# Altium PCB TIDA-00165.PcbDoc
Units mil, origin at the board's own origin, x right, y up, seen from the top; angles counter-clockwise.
Board outline 2800 x 235.83 mil, 4 copper layers (Top Layer, GND, VCC, Bottom Layer), stack 90 mil thick; 67 components, 45 nets, 220 pads, 72 vias.
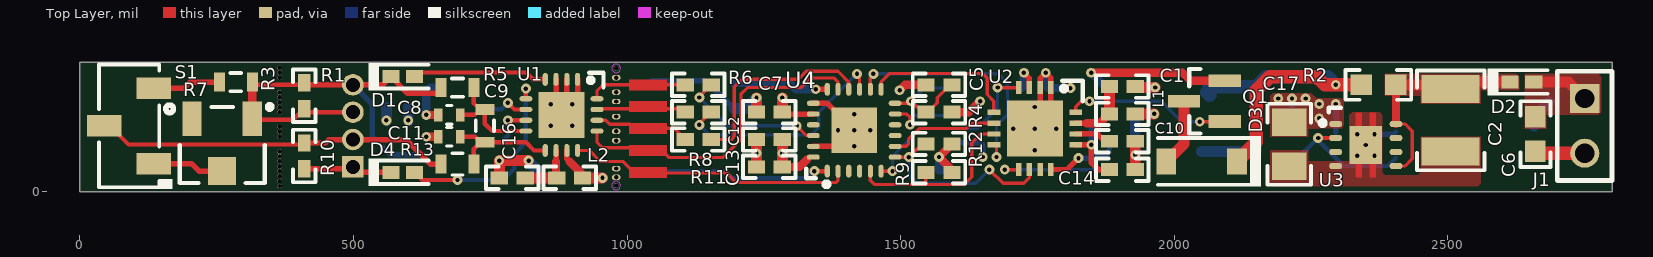
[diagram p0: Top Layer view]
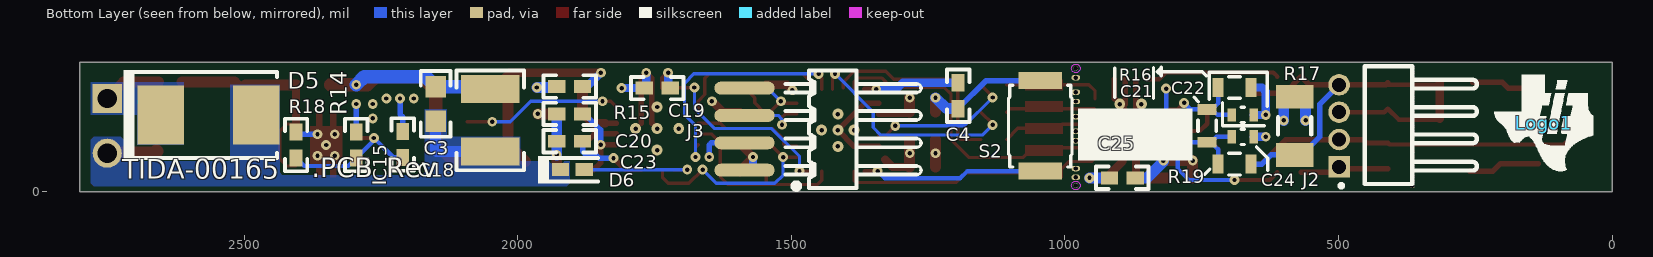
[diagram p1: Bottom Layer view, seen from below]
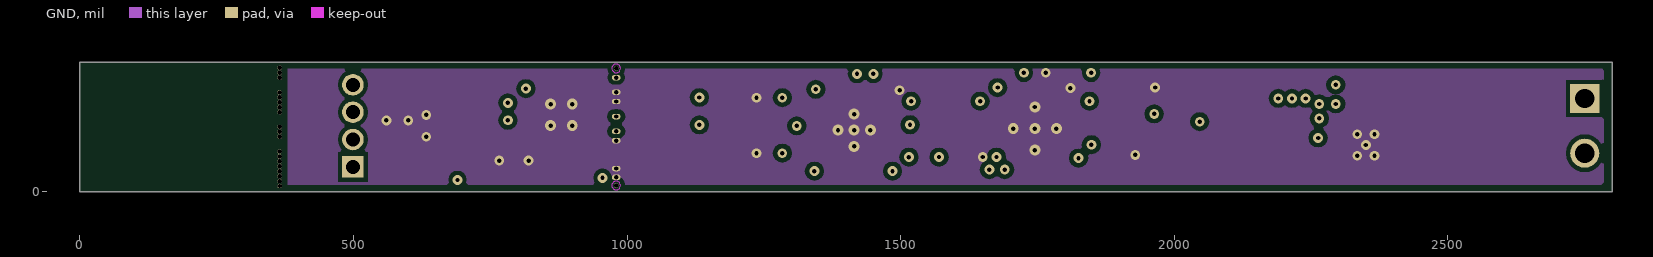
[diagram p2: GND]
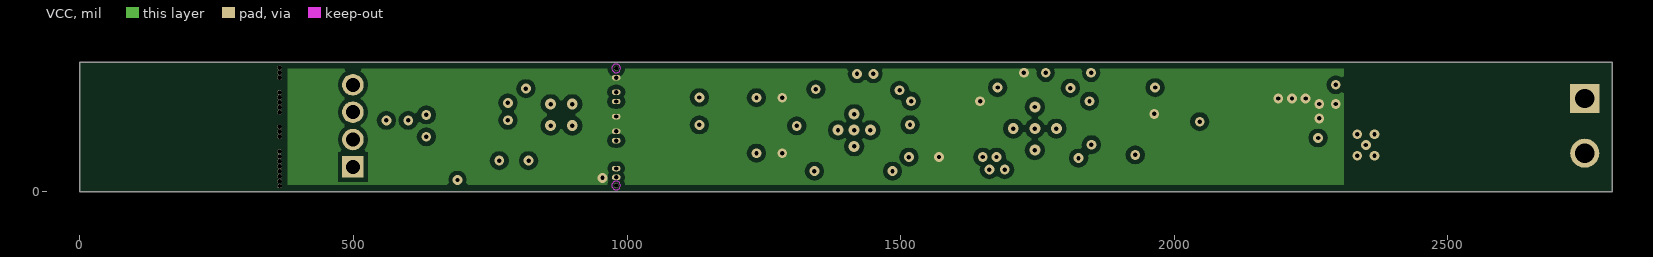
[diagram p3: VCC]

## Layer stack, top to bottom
Top Layer: signal copper 1.4
Dielectric: core 59.2, FR-4, Dk 4.8
GND: signal copper 1.4
Dielectric: prepreg 12.6, FR-4, Dk 4.8
VCC: signal copper 1.4
Dielectric: core 12.6, FR-4, Dk 4.8
Bottom Layer: signal copper 1.4

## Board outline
0,0 2800,0 2800,235.83 0,235.83

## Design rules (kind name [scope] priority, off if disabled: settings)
Clearance "Copper to 25.59 Mils Drill" [InPolygon] p1: gap=8
Clearance [All] p2: gap=4.92
DiffPairsRouting [All] p1: maxlimit=393.7 minlimit=4.92 mostfreqgap=5.91 maxuncoupledlength=500
FabricationTestPointUsage FabricationTestPointUsage_1 [All] p1: valid=0 allowmultiple=FALSE
FabricationTestpoint FabricationTestpoint_1 [All] p1: side=3 testpointundercomponent=TRUE minsize=40 maxsize=100 preferedsize=60 minholesize=0 maxholesize=40 preferedholesize=32 testpointgrid=1 allowsidetop=TRUE allowsidebottom=TRUE usegrid=TRUE gridtolerance=0.01
HoleSize [All] p1: absolutevalues=TRUE maxlimit=236.22 minlimit=7.87 maxpercent=80.000 minpercent=20.000
HoleSize FabricationTestpoint [All] p2 off: absolutevalues=TRUE maxlimit=100 minlimit=1 maxpercent=80.000 minpercent=20.000
HoleSize FabricationTestPointUsage [All] p3 off: absolutevalues=TRUE maxlimit=100 minlimit=1 maxpercent=80.000 minpercent=20.000
PlaneClearance [All] p1: clearance=19.68
PlaneConnect [All] p1: planeconnectstyle=Relief reliefexpansion=15.75 reliefentries=4 reliefconductorwidth=5.91 reliefairgap=5.91
PolygonConnect [All] p1: connectstyle=Direct reliefconductorwidth=5.91 reliefentries=4 polygonreliefangle="90 Angle" airgapwidth=10
RoutingCorners [All] p1: cornerstyle=45-Degree minsetback=49.21 maxsetback=49.21
RoutingVias [All] p1: holewidth=12 width=24 viastyle="Through Hole" minholewidth=8 minwidth=18 maxholewidth=16 maxwidth=30
SilkscreenOverComponentPads [All] p1: minsilkscreentomaskgap=10
SolderMaskExpansion [All] p1: expansion=2.5
Width [All] p1: maxlimit=100 minlimit=6 preferedwidth=6
20 further rules are at their usual default settings.

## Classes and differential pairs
pad class "Except Break Out PADS": C1-1 C1-2 C2-1 C2-2 C3-1 C3-2 C4-1 C4-2 C5-1 C5-2 C6-1 C6-2 C7-1 C7-2 C8-1 C8-2 C9-1 C9-2 C10-1 C10-2 C11-1 C11-2 C12-1 C12-2 C13-1 C13-2 C14-1 C14-2 C15-1 C15-2 C16-1 C16-2 C17-1 C17-2 C18-1 C18-2 C19-1 C19-2 C20-1 C20-2 C21-1 C21-2 C22-1 C22-2 C23-1 C23-2 C24-1 C24-2 C25-1 C25-2 D1-1 D1-2 D2-1 D2-2 D3-1 D3-2 D4-1 D4-2 D5-1 D5-2 D6-1 D6-2 J1-1 J1-2 J2-1 J2-2 J2-3 J2-4 J3-1 J3-2 J3-3 J3-4 L1-1 L1-2 L2-1 L2-2 Q1-1 Q1-2 Q1-3 R1-1 R1-2 R2-1 R2-2 R3-1 R3-2 R4-1 R4-2 R5-1 R5-2 R6-1 R6-2 R7-1 R7-2 R7-3 R8-1 R8-2 R9-1 R9-2 R10-1 R10-2 R11-1 R11-2 R12-1 R12-2 R13-1 R13-2 R14-1 R14-2 R15-1 R15-2 R16-1 R16-2 R17-1 R17-2 R18-1 R18-2 R19-1 R19-2 S1-1 S1-2 S1-3 S2-1 S2-2 U1-1 U1-2 U1-3 U1-4 U1-5 U1-6 U1-7 U1-8 U1-9 U1-10 U1-11 U1-12 U1-13 U1-14 U1-15 U1-16 U1-17 U2-1 U2-2 U2-3 U2-4 U2-5 U2-6 U2-7 U2-8 U2-9 U2-10 U2-11 U2-12 U2-13 U2-14 U2-15 U2-16 U2-17 U3-1 U3-2 U3-3 U3-4 U3-5 U3-6 U3-7 U3-8 U3-9 U4-1 U4-2 U4-3 U4-4 U4-5 U4-6 U4-7 U4-8 U4-9 U4-10 U4-11 U4-12 U4-13 U4-14 U4-15 U4-16 U4-17 U4-18 U4-19 U4-20 U4-21 U4-22 U4-23 U4-24 U4-25
pad class "BreakOut PADS": Free-0
pad class "Drill 25.59": J2-1 J2-2 J2-3 J2-4
component class Sheet-2: C1 C2 C3 C6 C10 C14 C15 C17 C18 C19 C20 C23 D2 D3 D5 D6 J1 L1 Q1 R2 R9 R12 R14 R15 R18 U2 U3
component class AssemblyNote: ZZ1 ZZ2 ZZ3 ZZ4
component class Logo: Logo1
component class Sheet-4: !PCB1 Logo1 ZZ1 ZZ2 ZZ3 ZZ4
component class Sheet-3: 22 C4 C5 C7 C8 C9 C11 C12 C13 C16 C21 C22 C24 C25 D1 D4 J2 J3 L2 R1 R3 R4 R5 R6 R7 R8 R10 R11 R13 R16 R17 R19 S1 S2 U1 U4

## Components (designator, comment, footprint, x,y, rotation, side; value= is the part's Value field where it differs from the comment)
C1 "C1005X5R0J104K" 0402 1905,191.81 r0 top (schematic designator C7)
C2 "GRM32ER71H106KA12L" 1210 2505,130 r270 top (schematic designator C4)
C3 "C1608X7R2A103K" 0603 2150,160 r270 bottom (schematic designator C9)
C4 "GRM155R60J474KE19D" 0402 1195,175 r270 bottom (schematic designator C22)
C5 "GRM155R70J222KA01D" 0402 1570,195 r180 top (schematic designator C26)
C6 "C1608X7R2A103K" 0603 2660,105 r270 top (schematic designator C2)
C7 "C1005X5R0J104K" 0402 1260,145 r180 top (schematic designator C24)
C8 "GRM155R72A272KA01D" 0402S 675,140 r180 top (schematic designator C19)
C9 "C0603C273K1RACTU" 0603S 740,120 r270 top (schematic designator C20)
C10 "GRM155R60J102KA01D" 0402 1905,91.79 r0 top
C11 "GRM155R72A272KA01D" 0402S 675,100 r0 top (schematic designator C21)
C12 "C1005X5R0J475M050BC" 0402 1260,95 r180 top (schematic designator C25)
C13 "C1005X5R0J104K" 0402 1260,45 r180 top (schematic designator C23)
C14 "GRM155R60J224KE01D" 0402 1905,40 r0 top (schematic designator C11)
C15 "GRM155R70J103KA01D" 0402 2210,86 r270 bottom (schematic designator C1)
C16 "GRM155R60J224KE01D" 0402 790,25 r180 top (schematic designator C17)
C17 "GRM21BR70J106KE76L" 0805_HV 2210,86.38 r270 top (schematic designator C3)
C18 "GRM32ER71H106KA12L" 1210 2050,130 r270 bottom (schematic designator C8)
C19 "C1005X5R0J104K" 0402 1745,189 r0 bottom (schematic designator C6)
C20 "GRM155R71E682KA01D" 0402 1905,141.79 r0 bottom (schematic designator C12)
C21 "GRM155R72A182KA01D" 0402S 675,140 r0 bottom (schematic designator C16)
C22 "C0603C183K1RACTU" 0603S 740,120 r90 bottom (schematic designator C15)
C23 "GRM155R61A394KE15D" 0402 1905,91.79 r0 bottom (schematic designator C13)
C24 "GRM155R72A182KA01D" 0402S 675,100 r180 bottom (schematic designator C14)
C25 "GRM155R60J224KE01D" 0402 895,25 r180 bottom (schematic designator C18)
D1 "ZHCS350TA" SOD-523 590,210 r0 top (schematic designator D5)
D2 "BAT41KFILM" SOD-523 2635,200 r0 top (schematic designator D1)
D3 "MMSZ4686T1G" SOD-123 2049.99,54.98 r180 top (schematic designator D4)
D4 "ZHCS350TA" SOD-523 590,35 r0 top (schematic designator D6)
D5 "SM6T39CA" SMB 2565,140 r180 bottom (schematic designator D2)
D6 "BAT41KFILM" SOD-523 1899.98,40.02 r180 bottom (schematic designator D3)
J1 "5-534206-1" CONN_534206-1 2750,120 r270 top
J2 "850-10-004-20-001000" Mill-Max_850-10-004-20-001000 365,120 r90 bottom
J3 "850-10-004-40-001000" Mill-max_850-10-004-40-001000 1424,114 r90 bottom
L1 "BLM15HG102SN1D" 0402 1905,141.79 r180 top
L2 "BLM15HG102SN1D" 0402 895,25 r180 top
Logo1 "Texas Instruments" TI_Symbol_Overlay_Small 125,125 r180 bottom
Q1 "MMBT3904" SOT-23 2055,165 r180 top
R1 "CRCW04020000Z0ED" 0402 410,175 r90 top (schematic designator R11)
R2 "RT0603DRE07100RL" 0603 2373,195 r180 top (schematic designator R1)
R3 "RG1608P-301-B-T5" 0603S 285,200 r0 top (schematic designator R13)
R4 "CRCW040247K0JNED" 0402 1570,145 r0 top (schematic designator R23)
R5 "RG1608P-4121-B-T5" 0603S 690,190 r0 top (schematic designator R12)
R6 "CRCW040247R0JNED" 0402 1130,195 r180 top (schematic designator R22)
R7 "3223W-1-501E" Bourns_3223W 260,85 r270 top (schematic designator R14)
R8 "CRCW040247R0JNED" 0402 1130,145 r180 top (schematic designator R18)
R9 "CRCW0402100KJNED" 0402 1570,35 r180 top (schematic designator R7)
R10 "CRCW04020000Z0ED" 0402 410,65 r90 top (schematic designator R16)
R11 "CRCW040247R0JNED" 0402 1130,95 r0 top (schematic designator R21)
R12 "CRCW0402100KJNED" 0402 1570,87 r0 top (schematic designator R6)
R13 "RG1608P-4121-B-T5" 0603S 690,50 r0 top (schematic designator R15)
R14 "CRCW040222K1FKED" 0402 2295,85 r90 bottom (schematic designator R2)
R15 "CRCW040220R0FKED" 0402 1905,191.81 r0 bottom (schematic designator R5)
R16 "RG1608P-4121-B-T5" 0603S 690,190 r0 bottom (schematic designator R10)
R17 "PFC-W1206R-12-3241-B" 1206L 580,120 r270 bottom (schematic designator R9)
R18 "CRCW040212K4FKED" 0402 2405,85 r270 bottom (schematic designator R3)
R19 "RG1608P-4121-B-T5" 0603S 690,50 r0 bottom (schematic designator R8)
S1 "CAS-120TA" SW_CAS-120TA 90,120 r180 top
S2 "SKRKAEE010" SW_SKRKAEE010 1045,120 r270 bottom
U1 "ADS1220IRVA" RVA0016A 880,140 r270 top (schematic designator U3)
U2 "DAC161S997RGH" RGH0016A 1745,115 r270 top
U3 "TPS7A1601DRB" DRB0008A 2350,85 r0 top (schematic designator U1)
U4 "MSP430FR5738IRGE" RGE0024G 1415,112 r90 top
ZZ1 "These assemblies must comply with workmanship standards IPC-A-610 Class 2, unless otherwise specified." AssemblyNote 187.21,1454.22 r0 top (schematic designator ZZ4)
ZZ2 "These assemblies must be clean and free from flux and all contaminants. Use of no clean flux is not acceptable." AssemblyNote 185.87,1391.83 r0 top (schematic designator ZZ3)
ZZ3 "This Assembly Note is for PCB labels only" AssemblyNoteLabel 185.91,1319.68 r0 top
ZZ4 "These assemblies are ESD sensitive, ESD precautions shall be observed." AssemblyNote 183.85,1242.97 r0 top (schematic designator ZZ2)

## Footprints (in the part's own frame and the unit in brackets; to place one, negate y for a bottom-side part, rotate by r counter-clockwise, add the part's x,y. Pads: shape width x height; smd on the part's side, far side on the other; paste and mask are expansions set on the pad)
0402 [mm] "0402 from SM-752 data"
  rect 0.8x0.6 smd: 1(-0.6,0) 2(0.6,0)
  silkscreen extent -1.22,-0.52 1.22,0.52, body extent -0.55,-0.3 0.55,0.3, height 0.6
0402S [mil] "Based on C0402S footprint from PADS legacy"
  rect 15x24 smd: 1(-20,0) 2(20,0)
  body extent -22,-12 22,12, height 24
0603 [mm] "0603 from SM-752 data"
  rect 1x0.95 smd: 1(-0.8,0) 2(0.8,0)
  silkscreen extent -1.52,-0.69 1.52,0.69, body extent -0.87,-0.47 0.87,0.47, height 0.85
0603S [mil]
  rect 20x35 smd: 1(-30,0) 2(30,0)
  silkscreen extent -10,-17 10,17, body extent -34,-19 34,19, height 33
0805_HV [mil] "0805 with 30mil clearance between pads"
  rect 50x63 smd: 1(-40,0) 2(40,0)
  silkscreen extent -74,-40 74,40, body extent -43,-29 43,29, height 43
1206L [mm] "1206 from SM-752 data"
  rect 1.1x1.75 smd: 1(-1.35,0) 2(1.35,0)
  silkscreen extent -0.4,-0.77 0.4,0.77, body extent -1.7,-0.9 1.7,0.9, height 1.35
1210 [mm] "1210 from SM-752 data"
  rect 1.3x2.7 smd: 1(-1.45,0) 2(1.45,0)
  silkscreen extent -2.32,-1.57 2.32,1.57, body extent -1.7,-1.35 1.7,1.35, height 1.35
AssemblyNote [mil] "Assembly Note"
AssemblyNoteLabel [mil] "Assembly Note for PCB Labels"
Bourns_3223W [mm] "Bourns"
  rect 1.6x0.9 smd: 1(-1.215,1.4) 3(-1.215,-1.4)
  rect 1.3x1.3 smd: 2(1.215,0)
  silkscreen extent -1.87,-1.97 1.76,2.3, body extent -1.76,-1.97 1.76,1.97, height 4.17
CONN_534206-1 [mm] "TE_CONNECTIVITY"
  rect 1.35x1.35 hole 0.89: 1(-1.27,0)
  round 1.35 hole 0.89: 2(1.27,0)
  silkscreen extent -2.54,-1.27 2.54,1.27, body extent -2.51,-1.27 2.51,1.27, height 8.65
DRB0008A [mm] "SON, 8-Leads, Body 3x3mm, Pitch 0.65mm, Thermal Pad 1.75x1.5mm, TI Recommended"
  oval 0.6x0.3 smd: 1(-1.4,0.975) 2(-1.4,0.325) 3(-1.4,-0.325) 4(-1.4,-0.975) 5(1.4,-0.975) 6(1.4,-0.325) 7(1.4,0.325) 8(1.4,0.975)
  rect 1.5x1.75 smd paste-0.75: 9(0,0)
  Top Layer region: -0.465,-1.5 -0.465,-0.875 -0.75,-0.875 -0.75,0.875 -0.465,0.875 -0.465,1.5 -0.185,1.5 -0.185,0.875 0.185,0.875 0.185,1.5 0.465,1.5 0.465,0.875 0.75,0.875 0.75,-0.875 0.465,-0.875 0.465,-1.5 0.185,-1.5 0.185,-0.875 -0.185,-0.875 -0.185,-1.5
  silkscreen extent -1.72,1.53 -1.15,1.73, body extent -1.57,-1.57 1.58,1.58, height 1.01
Mill-Max_850-10-004-20-001000 [mm] "Mill-Max"
  rect 1x1 hole 0.65: 1(-1.905,3.4)
  round 1 hole 0.65: 2(-0.635,3.4) 3(0.635,3.4) 4(1.905,3.4)
  silkscreen extent -2.83,-3 2.76,3.35, body extent -2.73,-3 2.73,3.59, height 2.21
Mill-max_850-10-004-40-001000 [mm] "Mill-max"
  oval 0.6x2.8 smd: 1(-1.905,4.1) 2(-0.635,4.1) 3(0.635,4.1) 4(1.905,4.1)
  silkscreen extent -2.78,-4.1 2.73,2.21, body extent -2.73,-4.08 2.74,5.43, height 2.13
RGE0024G [mm] "QFN, 24-Leads, Body 4x4mm, Pitch 0.5mm, Thermal Pad 2.1x2.1mm, TI Recommended"
  oval 0.6x0.24 smd mask+0.07: 1(-1.9,1.25) 2(-1.9,0.75) 3(-1.9,0.25) 4(-1.9,-0.25) 5(-1.9,-0.75) 6(-1.9,-1.25) 13(1.9,-1.25) 14(1.9,-0.75) 15(1.9,-0.25) 16(1.9,0.25) 17(1.9,0.75) 18(1.9,1.25)
  oval 0.24x0.6 smd mask+0.07: 7(-1.25,-1.9) 8(-0.75,-1.9) 9(-0.25,-1.9) 10(0.25,-1.9) 11(0.75,-1.9) 12(1.25,-1.9) 19(1.25,1.9) 20(0.75,1.9) 21(0.25,1.9) 22(-0.25,1.9) 23(-0.75,1.9) 24(-1.25,1.9)
  rect 2.1x2.1 smd paste-1.05 mask+0.07: 25(0,0)
  silkscreen extent -2.22,1.79 -1.79,2.22, body extent -2.07,-2.07 2.07,2.07, height 1.01
RGH0016A [mm] "QFN, 16-Leads, Body 4x4mm, Pitch 0.5mm, TI Recommended"
  rect 0.6x0.25 smd: 1(-1.9,0.75) 2(-1.9,0.25) 3(-1.9,-0.25) 4(-1.9,-0.75) 9(1.9,-0.75) 10(1.9,-0.25) 11(1.9,0.25) 12(1.9,0.75)
  rect 0.25x0.6 smd: 5(-0.75,-1.9) 6(-0.25,-1.9) 7(0.25,-1.9) 8(0.75,-1.9) 13(0.75,1.9) 14(0.25,1.9) 15(-0.25,1.9) 16(-0.75,1.9)
  rect 2.6x2.6 smd paste-1.3: 17(0,0)
  silkscreen extent -2.22,1.28 -1.27,2.22, body extent -2.05,-2.05 2.05,2.05, height 0.81
RVA0016A [mm] "QFN, 16-Leads, Body 3.5x3.5mm, Pitch 0.5mm, Thermal Pad 2.14x2.14mm, TI Recommended"
  oval 0.6x0.24 smd mask+0.07: 1(-1.65,0.75) 2(-1.65,0.25) 3(-1.65,-0.25) 4(-1.65,-0.75) 9(1.65,-0.75) 10(1.65,-0.25) 11(1.65,0.25) 12(1.65,0.75)
  oval 0.24x0.6 smd mask+0.07: 5(-0.75,-1.65) 6(-0.25,-1.65) 7(0.25,-1.65) 8(0.75,-1.65) 13(0.75,1.65) 14(0.25,1.65) 15(-0.25,1.65) 16(-0.75,1.65)
  rect 2.14x2.14 smd paste-1.07 mask+0.07: 17(0,0)
  silkscreen extent -1.95,1.29 -1.29,1.95, body extent -1.8,-1.8 1.8,1.8, height 1.01
SMB [mil] "Molded Diode, 2-Leads, Body 5.4x3.6mm, IPC Medium Density, based on OnSemi component dimensions"
  rect 85x107.99 smd: 1(-87.01,0) 2(87.01,0)
  silkscreen extent -155,-82 125,82, body extent -106,-71 106,71, height 91
SOD-123 [mm] "On Semi recommended land pattern"
  rect 0.915x1.22 smd: 1(-1.637,0) 2(1.637,0)
  silkscreen extent -2.74,-1.17 2.03,1.17, body extent -1.93,-0.9 1.93,0.9, height 1.35
SOD-523 [mm] "NXP Semiconductor recommended land pattern, nominal STEP model"
  rect 0.8x0.6 smd: 1(-0.55,0) 2(0.55,0)
  silkscreen extent -1.6,-0.64 1.2,0.64, body extent -0.8,-0.4 0.8,0.4, height 0.72
SOT-23 [mm] "SOT23, 3-Leads, Body 2.9x1.3mm, Pitch 0.95mm, Lead Span 2.5mm, IPC Medium Density"
  rect 1.5x0.6 smd: 1(-0.95,0.95) 2(-0.95,-0.95) 3(0.95,0)
  silkscreen extent 0.2,-1.5 0.7,1.5, body extent -1.16,-1.45 1.21,1.45, height 1
SW_CAS-120TA [mm] "COPAL ELECTRONICS"
  rect 1.6x1 smd: 1(-1.15,1.75) 2(1.15,0) 3(-1.15,-1.75)
  silkscreen extent -2,-2.85 1.4,2.92, body extent -1.4,-2.85 1.4,2.85, height 2.51
SW_SKRKAEE010 [mm] "Alps recommended land pattern"
  rect 0.8x2 smd: 1(-2.1,0) 2(2.1,0)
  body extent -2.4,-1.45 2.4,1.45, height 1.96
TI_Symbol_Overlay_Small [mil]
  silkscreen extent -90,-88 91,88

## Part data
C1 C7 C13 C19: "CAP, CERM, 0.1uF, 6.3V, +/-10%, X5R, 0402"
C2 C18: "CAP, CERM, 10uF, 50V, +/-10%, X7R, 1210"
C3 C6: "CAP, CERM, 0.01uF, 100V, +/-10%, X7R, 0603"
C4: "CAP, CERM, 0.47uF, 6.3V, +/-10%, X5R, 0402"
C5: "CAP, CERM, 2200pF, 6.3V, +/-10%, X7R, 0402"
C8 C11: "CAP, CERM, 2700pF, 100V, +/-10%, X7R, 0402"
C9: "CAP, CERM, 0.027uF, 100V, +/-10%, X7R, 0603"
C10: "CAP, CERM, 1000pF, 6.3V, +/-10%, X5R, 0402"
C12: "CAP, CERM, 4.7uF, 6.3V, +/-20%, X5R, 0402"
C14 C16 C25: "CAP, CERM, 0.22uF, 6.3V, +/-10%, X5R, 0402"
C15: "CAP, CERM, 0.01uF, 6.3V, +/-10%, X7R, 0402"
C17: "CAP, CERM, 10uF, 6.3V, +/-10%, X7R, 0805"
C20: "CAP, CERM, 6800pF, 25V, +/-10%, X7R, 0402"
C21 C24: "CAP, CERM, 1800pF, 100V, +/-10%, X7R, 0402"
C22: "CAP, CERM, 0.018uF, 100V, +/-10%, X7R, 0603"
C23: "CAP, CERM, 0.39uF, 10V, +/-10%, X5R, 0402"
D1 D4: "Diode, Schottky, 40V, 0.35A, SOD-523"
D2 D6: library part BAT41ZFILM, "DIODE SCHOTTKY 100V 0.2A SOD523"
D3: "Diode, Zener, 3.9V, 500mW, SOD-123"
D5: library part SMBJ40CA-13-F, "TVS DIODE 33.3VWM 69.7VC SMB"
J1: "Connector, Receptacle, 100mil, 2x1, Gold plated, TH"
J2: "Header, 4x1, 50mil, R/A, TH"
J3: "Header, 4x1, 50mil, R/A, SMT"
L1 L2: "0.25A Ferrite Bead, 1000 ohm @ 100MHz, SMD"
Logo1: library part TI_Logo, "Texas Instrument Corporate Signature"
Q1: library part "MMBT3904, Fairchild Semiconductor", "Transistor, NPN, 40V, 0.2A, SOT-23"
R1 R10: "RES, 0 ohm, 5%, 0.063W, 0402"
R2: "RES, 100 ohm, 0.5%, 0.1W, 0603"
R3: "RES, 300 ohm, 0.1%, 0.1W, 0603"
R4: "RES, 47k ohm, 5%, 0.063W, 0402"
R5 R13 R16 R19: "RES, 4.12k ohm, 0.1%, 0.1W, 0603"
R6 R8 R11: "RES, 47 ohm, 5%, 0.063W, 0402"
R7: "TRIMMER 500 OHM 0.125W SMD"
R9 R12: "RES, 100k ohm, 5%, 0.063W, 0402"
R14: "RES, 22.1k ohm, 1%, 0.063W, 0402"
R15: "RES, 20.0 ohm, 1%, 0.063W, 0402"
R17: "RES, 3.24k ohm, 0.1%, 0.333W, 1206"
R18: "RES, 12.4k ohm, 1%, 0.063W, 0402"
S1: "Switch, Slide, SPDT  100mA, SMT"
S2: "Switch, Push Button, SMD"
U1: "Low-Power, Low-Noise, 24-Bit Analog-to-Digital Converter for Small Signal Sensors, RVA0016A"
U2: "16-bit SPI Programmable DAC for 4-20mA Loops, RGH0016A"
U3: "60-V, 5-µA IQ, 100-mA, Low-Dropout Voltage Regulator with Enable and Power-Good, DRB0008A"
U4: "24 MHz Mixed Signal Microcontroller, 1024 B SRAM and 17 GPIOs, -40 to 85 degC, RGE0024G"
ZZ1 ZZ2 ZZ4: library part AssemblyNote
ZZ3: library part AssemblyNoteLabel

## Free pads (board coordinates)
  round 8 hole 8 unplated: 0(365,10) 0(365,19) 0(365,28) 0(365,37) 0(365,46) 0(365,55) 0(365,64) 0(365,73) 0(365,100) 0(365,109) 0(365,118) 0(365,145) 0(365,154) 0(365,163) 0(365,172) 0(365,181) 0(365,208) 0(365,217) 0(365,226) 0(980,11) 0(980,225)
  oval 16x10 hole 8: 0(980,26) 0(980,42) 0(980,93) 0(980,110) 0(980,137) 0(980,164.47) 0(980,181.47) 0(980,208)

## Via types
v1: diameter 18, hole 8, Top Layer to Bottom Layer, tented both sides, 58 vias
v2: diameter 20, hole 8, Top Layer to Bottom Layer, tented both sides, 14 vias

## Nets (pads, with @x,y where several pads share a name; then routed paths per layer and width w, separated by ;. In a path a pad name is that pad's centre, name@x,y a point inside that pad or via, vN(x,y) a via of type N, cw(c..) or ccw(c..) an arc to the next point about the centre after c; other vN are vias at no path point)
ADC_CLK: R8.2 U1.15 | length 164.4
  Top Layer w6: U1.15 946.12,151 1100.38,151 R8.2
ADC_CS: R6.2 U1.16 | length 180.4
  Top Layer w6: U1.16 944.96,183.96 956,195 R6.2
ADC_SIMO: R11.1 U1.14 | length 176
  Top Layer w6: U1.14 960.96,130.16 968.12,123 1005,123 1012.5,115.5 1085.88,115.5 R11.1
ADC_SOMI: U1.13 U4.17 | length 596.7
  Top Layer w6: U1.13 944.96,90.04 955,80 1061,80 ; 1061,78 1077,62 1175,62 1208,95 1208,178 1220,190 1317.39,190 1335.01,207.61 1377.39,207.61 1385.47,199.53 U4.17
AIN0: C9.2 C11.2 R13.2 U1.9 | length 210.8
  Top Layer w6: C9.2@732,90 C9.2
  Top Layer w8: C11.2 722,100 732,90 720,78 R13.2 ; C9.2 815.04,90 830,75.04 U1.9
AIN1: C8.1 C9.1 R5.2 U1.8 | length 200.3
  Top Layer w8: C8.1 721,140 C9.1@731,150 ; R5.2 720,161 C9.1@731,150 ; U1.8 753.53,110.47 740,124 C9.1 C9.1@731,150
AIN2: D4.2 U1.5 | length 370
  Top Layer w8: D4.2 625.65,21 v1(690,21) ; U1.5 v1(815.04,188)
  Bottom Layer w8: v1(690,21) 773,21 794.02,42.02 794.02,69.02 815.04,90.04 v1(815.04,188)
AIN3: D1.2 U1.4 | length 247.1
  Top Layer w8: D1.2 619.15,217.5 815.5,217.5 828.04,204.96 U1.4
DAC_CLK: U2.4 U4.6 | length 350.2
  Top Layer w6: U4.6 v1@1482.2,37.2 ; v1(1677,190) 1677.2,189.8 U2.4
  Bottom Layer w6: v1(1485,37.2) 1485,64.54 1535.46,115 1640.16,115 1677,151.84 v1(1677,190)
DAC_CS: U2.6 U4.8 | length 203.1
  Top Layer w6: U4.8 1510.24,82.47 1514.16,86.4 1514.16,95.23 1533.93,115 1620,115 1629.84,124.84 U2.6
DAC_SIMO: U2.5 U4.13 | length 284.8
  Top Layer w6: U4.13 1464.21,200.21 1479.81,215.81 1649.19,215.81 1658.19,206.81 1658.19,177.27 1670.2,165.26 U2.5
DAC_SOMI: U2.8 U4.14 | length 449.7
  Top Layer w6: U4.14 1444.53,207.53 v1@1451,214 ; U2.8 1675,80.67 v1(1675,63)
  Bottom Layer w6: v1(1450,215) 1678.06,215 1695,198.06 1695,140 1675,120 v1(1675,63)
DRDY: U1.12 U4.2 | length 518.7
  Top Layer w6: U1.12 930.42,75.04 950.46,55 992,55 1013,34 1182,34 1199.61,16.39 1381.39,16.39 1385.47,20.47 U4.2
ERR_LVL: R12.1 U2.10 U4.7 | length 365.7
  Top Layer w6: U4.7 v1(1515,62.79) 1539.21,87 R12.1 ; v1(1662,40) 1687,15 1725,15 1735.16,25.16 U2.10
  Bottom Layer w6: v1(1515,62.79) 1515,30 1530,15 1637,15 v1(1662,40)
GND: C1.2 C2.2 C4.2 C5.2 C7.2 C8.2 C10.2 C11.1 C12.2 C13.2 C14.2 C16.2 C17.2 C19.2 C20.2 C21.1 C23.2 C24.2 C25.2 J3.2 pad.0@980,26 pad.0@980,42 pad.0@980,93 pad.0@980,164.47 pad.0@980,181.47 R15.2 R16.1 R17.1 R18.1 S2.1 U1.1 U1.2 U1.3 U1.17 U2.1 U2.2 U2.17 U3.4 U3.9 U4.19 U4.23 U4.25 | length 1688.3
  Top Layer w10: U1.3 870.16,149.84 U1.17 909.53,169.53 U1.1 ; U1.17@889.84,159.68 U1.2 ; U4.23 1385.47,82.47 v2(1415,112) 1365.79,161.21 U4.19 ; v2(1745,115) 1754.84,124.84 U2.2 1754.84,206.84 v1(1765,217) 1774.53,207.47 U2.1 U2.17@1774.53,124.84
  Top Layer w15: v1(633,100) C11.1 ; v1(633,140) C8.2 ; v1(1498,185) 1508,195 C5.2
  Top Layer w20: C16.2 v1(766.38,56.38) v1(820,56.38) ; C13.2 v1(1236.38,70) C12.2 ; C7.2 v1(1236.38,171.38) ; C14.2 v1(1928.62,66.85) C10.2 ; C1.2 1930.43,190 v1(1965,190)
  Bottom Layer w10: S2.1 1143.7,202.68 C4.2 ; J3.2 1646,89 1650,85 v1(1650,63) ; v1(2365.74,104.68) 2401.06,104.68 R18.1
  Bottom Layer w15: v1(633,100) C24.2 ; C21.1 v1(633,140) 633,183 640,190 R16.1 ; v1(1765,217) 1765,192.62 C19.2 v1(1810,189)
  Bottom Layer w20: v1(560,130) R17.1@560,153.15 ; v1(600,130) R17.1@600,153.15 ; v1(820,56.38) 820,55 850,25 C25.2 ; C4.2 1216.38,151.38 v1(1236.38,171.38) ; v1(1928.62,66.85) C23.2 C20.2 ; R15.2 1930.43,190 v1(1965,190)
  other v1: 2334.25,65.31 2365.75,65.31 2350,85 2334.25,104.68
  other v2: 1745,75.63 1415,82.47 1385.47,112 1444.53,112 1705.63,115 1784.37,115 860.31,120.31 899.68,120.31 1415,141.53 1745,154.37 860.31,159.68 899.68,159.68
LOOP-: C3.2 C6.2 C18.2 D5.2 D6.1 J1.2 | length 245.8
  Top Layer w25: C6.2 2663.5,70 J1.2
  Bottom Layer w20: C18.2 2147.91,72.91 2150,75 C3.2
LOOP_PWR: C3.1 C18.1 D3.1 R2.2 | length 604.4
  Top Layer w25: D3.1 2150,90.53 2150,185 2175,210 2260,210 2275,195 v1(2295,195) R2.2
  Bottom Layer w25: C18.1@2059.41,181.5 C18.1@2064.41,176.5 ; C18.1@2064.41,191.5 C3.1 2168.5,210 2280,210 v1(2295,195)
NDAC_ERROR: R9.2 U2.7 U4.5 | length 342.5
  Top Layer w6: U4.5 1444.53,20.47 1452,13 1546,13 ; R9.2 1546,34.62 1546,13 ; U2.7 1646,105.16 1630,89.16 1630,26.5 1616.5,13 1546,13
NetC1_1: C1.1 L1.2 U2.15 | length 118.6
  Top Layer w10: U2.15 1840,124.84
  Top Layer w15: 1840,124.84 1864.43,124.84 L1.2
  Top Layer w20: L1.2 C1.1
NetC2_1: C2.1 D2.1 R2.1 U3.5 U3.8 | length 409.3
  Top Layer w6: U3.5 2421.61,46.61 2435,60 2435,110 2421.61,123.39 U3.8
  Top Layer w15: U3.8 R2.1@2405.12,194.38
  Top Layer w20: R2.1 2497.09,195 C2.1 2517.91,200 D2.1
NetC4_1: C4.1 U4.18 | length 175.7
  Top Layer w10: v1(1344.8,186.8) U4.18
  Bottom Layer w15: C4.1 1296.38,198.62 1308.2,186.8 v1(1344.8,186.8)
NetC5_1: C5.1 J3.4 R4.1 U4.12 | length 216
  Top Layer w6: U4.12 1515.21,161.21 v1(1519,165) 1539,145 R4.1 1550,145 1567,162 1567,171 1591,195 C5.1
  Bottom Layer w6: v1(1519,165) 1543,189 J3.4
NetC6_1: C6.1 D2.2 D5.1 J1.1 | length 179
  Top Layer w20: D2.2 2720,200 J1.1 ; C6.1 C6.1@2666.5,130
  Bottom Layer w20: D5.1@2657.01,120 2657.01,136.01 D5.1@2685,164 ; J1.1@2744,164 J1.1
NetC10_1: C10.1 U2.14 | length 67.1
  Top Layer w10: U2.14 1860,105.16 1873.37,91.79 C10.1
NetC14_1: C14.1 C20.1 U2.13 | length 171.8
  Top Layer w10: U2.13 v1(1848.47,85.47) 1848.47,52.53 1861,40 C14.1
  Bottom Layer w10: v1(1848.47,85.47) 1848.47,112.47 1877.79,141.79 C20.1
NetC15_2: C15.2 R14.1 R18.2 U3.2 | length 271.3
  Top Layer w8: v1(2262.8,97.8) U3.2
  Bottom Layer w8: C15.2@2210.2,62.58 2227.58,62.58 v1(2262.8,97.8) 2262.8,93.58 R14.1 2309.83,46.55 2390.17,46.55 R18.2
NetC16_1: C16.1 L2.2 U1.10 | length 108.3
  Top Layer w10: 870.16,55 U1.10
  Top Layer w15: 870.16,55 870.16,26.22 L2.2
  Top Layer w20: C16.1 L2.2
NetC23_1: C23.1 U2.12 | length 139
  Top Layer w10: U2.12 1804.2,40.2 v1(1825,61)
  Bottom Layer w10: v1(1825,61) 1850.76,61 1856,66.24 1874.24,66.24 1881.38,73.38 C23.1
NetD1_1: D1.1 J2.3 J2.4 R1.1 R1.2 R3.2 R5.1 R7.1 R17.2 R19.1 | length 895.3
  Top Layer w8: R7.1@315,132.95 R7.1 316.95,131 389.62,131 R1.1 416.38,145 J2.3 ; R3.2 320,195 R1.2@410,195
  Top Layer w10: R1.2 413.62,195 J2.4 553.35,195 D1.1 598.85,179.5 660,179.5 R5.1
  Top Layer w15: R7.1@315,132.95 R3.2@315,198.62
  Bottom Layer w10: J2.4 534.55,159.31 534.55,100.02 567.72,66.85 R17.2 623.15,66.85 640,50 R19.1
NetD3_2: D3.2 Q1.3 | length 123.3
  Top Layer w20: D3.2 2017.6,87.06 Q1.3
NetD4_1: D4.1 J2.1 R10.1 | length 158.9
  Top Layer w10: R10.1 J2.1@495.24,41.38 ; J2.1 508.86,35 D4.1
NetD6_2: D6.2 U2.9 | length 213.6
  Top Layer w6: v1(1690,40) U2.9@1715.28,40
  Bottom Layer w6: v1(1690,40) D6.2
NetJ2_2: J2.2 R10.2 R13.1 S1.2 | length 651.7
  Top Layer w8: S1.2 55,120 89,86 407.38,86 R10.2
  Top Layer w10: R10.2 448.62,88.62 455,95 J2.2 596,95 641,50 R13.1
NetJ3_3: J3.3 U4.11 | length 124.7
  Top Layer w6: U4.11 1511.3,141.53 1517,135.83 v1(1517,122)
  Bottom Layer w6: v1(1517,122) 1517,132 1524,139 J3.3
NetQ1_1: Q1.1 U2.16 | length 302.6
  Top Layer w6: U2.16 1819.8,154.8 1830,165 v1(1845,165) ; v1(2046.4,127.6) Q1.1
  Bottom Layer w6: v1(1845,165) 1976,165 2013.4,127.6 v1(2046.4,127.6)
NetQ1_2: Q1.2 R15.1 | length 300.8
  Top Layer w6: Q1.2@2077.8,207 Q1.2@2082.4,202.4
  Top Layer w15: v1(1848,217) 2015,217 2029.6,202.4 2082.4,202.4 Q1.2
  Bottom Layer w15: v1(1848,217) 1873.19,191.81 R15.1
NetR3_1: R3.1 S1.3 | length 124.3
  Top Layer w10: S1.3 190,188.9 201.1,200 R3.1
NetR6_1: R6.1 U4.22 | length 268.8
  Top Layer w6: v1@1131.2,172.57 R6.1 ; v1(1310,120) 1327.84,102.16 U4.22
  Bottom Layer w6: v1(1131.96,171.81) 1183.77,120 v1(1310,120)
NetR7_2: R7.2 S1.1 | length 130.5
  Top Layer w10: S1.1 203.9,51.1 217.83,37.17 R7.2
NetR8_1: R8.1 U4.15 | length 420.5
  Top Layer w6: v1@1131.2,122.57 R8.1 ; v1(1420,215) 1424.84,210.16 U4.15
  Bottom Layer w6: v1(1131.96,121.81) 1150.69,103.08 1336.08,103.08 1350,117 1350,145 v1(1420,215)
NetR11_2: R11.2 U4.16 | length 374.1
  Top Layer w6: R11.2 1190,95 1196,101 1196,191 1210,205 1313,205 1327.61,219.61 1385.39,219.61 1405.16,199.84 U4.16@1405.16,189.8
REFN0: C21.2 C22.2 R16.2 U1.6 | length 173.7
  Top Layer w8: v1(782,162) 794.16,149.84 U1.6@810,149.84
  Bottom Layer w6: C22.2@731,150 C22.2
  Bottom Layer w8: C21.2 721,140 731,150 720,161 R16.2 ; C22.2 770,150 v1(782,162)
REFP0: C22.1 C24.1 R19.2 U1.7 | length 202.7
  Top Layer w8: v1(782,130.16) U1.7
  Bottom Layer w6: C22.1@733,90 C22.1
  Bottom Layer w8: C24.1 723,100 733,90 720,77 R19.2 ; C22.1 770,90 782,102 v1(782,130.16)
SW: S2.2 U4.1 | length 331.4
  Top Layer w8: v1(1342.2,37.2) U4.1
  Bottom Layer w8: S2.2 1178.18,37.32 1191,24.5 1329.5,24.5 v1(1342.2,37.2)
VCC: C7.1 C12.1 C13.1 C15.1 C17.1 C19.1 C25.1 J3.1 L1.1 L2.1 pad.0@980,110 pad.0@980,137 pad.0@980,208 R4.2 R9.1 R12.2 R14.2 U1.11 U2.3 U3.1 U4.20 U4.24 | length 699.3
  Top Layer w10: U1.11 889.84,60.16 895,55 ; C7.1 1287.09,141.53 U4.20 ; v1(1725,217) 1735.16,206.84 U2.3
  Top Layer w15: 895,55 918.62,31.38 L2.1 ; C13.1 1315,45 1328.34,58.34 ; R9.1 1593.62,39.38 v1(1570,63) 1570,63.38 R12.2 ; R4.2 1625,145 v1(1645,165)
  Top Layer w20: L2.1 v1(955,25) ; C13.1 v1(1283.62,70) C12.1 ; C7.1 v1(1283.62,171.38) ; L1.1 v1(1963.21,141.79)
  Bottom Layer w10: C15.1 2210,136 2215,141 v1(2215,170) ; R14.2 v1(2295,160)
  Bottom Layer w15: v1(1570,63) 1570,39 J3.1 ; C19.1 1725,192.62 v1(1725,217)
  Bottom Layer w20: C25.1 v1(955,25)
  other v1: 2265,133.62 2265,160 2190,170 2240,170
pads on no net: R7.3 U2.11 U3.3 U3.6 U3.7 U4.3 U4.4 U4.9 U4.10 U4.21

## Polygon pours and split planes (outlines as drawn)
VCC on Top Layer "Top Layer-No Net 3" (solid, remove dead copper, pour order 21): 2175,175 2180,180 2250,180 2260,170 2305,170 2310,165 2310,120 2305,115 2245,115 2245,100 2175,100
GND on Top Layer "Top Layer-No Net 4" (solid, remove dead copper, pour order 23): 2175,75 2175,20 2175,15 2180,10 2555,10 2560,15 2560,100 2450,100 2450,35 2445,30 2385,30 2380,35 2380,140 2375,145 2325,145 2320,140 2320,55 2245,55 2245,75 2175,75
NetC2_1 on Top Layer "Top Layer-No Net 1" (solid, remove dead copper, pour order 19): 2385,215 2385,175 2450,175 2450,160 2560,160 2560,185 2630,185 2630,210 2625,215 2385,215
NetC6_1 on Top Layer "Top Layer-No Net" (solid, remove dead copper, pour order 17): 2775,215 2780,210 2780,145 2775,140 2680,140 2680,115 2640,115 2640,215 2775,215
NetC6_1 on Bottom Layer "Bottom Layer-No Net 1" (solid, remove dead copper, pour order 15): 2780,200 2780,140 2695,140 2695,85 2610,85 2610,200
LOOP- on Bottom Layer "Bottom Layer-No Net" (solid, remove dead copper, pour order 13): 2775,100 2780,95 2780,15 2775,10 1910,10 1905,15 1905,55 1995,55 1995,100 2125,100 2130,105 2130,150 2170,150 2170,35 2175,30 2430,30 2435,35 2435,195 2525,195 2525,60 2530,55 2715,55 2720,60 2720,95 2725,100 2775,100
VCC on VCC "Top Layer-No Net 2" (solid, remove dead copper, pour order 6): 2310,224 450,224 380,223.98 380,12 2310,12
GND on GND "Top Layer-No Net 2" (solid, remove dead copper, pour order 8): 1742.52,223.98 2275,224 2782,224 2785,221 2785,17 2780,12 380,12 380,223.98

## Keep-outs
Keep-Out Layer:
  circle w1: c980,11 r8
  circle w1: c980,225 r8
  text ".Layer_Name" at 577,-858.49 h60

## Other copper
Top Layer:
  rectangle net ADC_CS: 1003,185 1073,205
  rectangle net ADC_CLK: 1003,145 1073,165
  rectangle net ADC_SIMO: 1003,105 1073,125
  rectangle net ADC_SOMI: 1003,65 1073,85
  rectangle net DRDY: 1003,25 1073,45
  text ".Layer_Name" at 577,-858.49 h60
GND:
  text "Layer2_GND Plane" at 597.64,-861 h60
VCC:
  text "Layer3_VCC Plane" at 598.25,-860.93 h60
Bottom Layer:
  text ".Layer_Name" at 577,-858.49 h60

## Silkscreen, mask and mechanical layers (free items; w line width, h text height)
Top Overlay:
  circle w10: c2271,125 r4
  circle w10: c1798.41,188.19 r4
  circle w10: c1364.17,13.32 r4
  circle w10: c933.41,203.35 r4
  circle w10: c164,151 r7
  lines w6: 670,83 680,83 ; 670,117 680,117 ; 670,123 680,123 ; 670,157 680,157 ; 680,30.32 700,30.32 ; 680,69.69 700,69.69
  text ".Layer_Name" at 577,-858.49 h60
Bottom Overlay:
  rectangle: 766.38,56.38 976.38,151.38
  lines w6: 629,39 629,61 650,82 ; 630,156 630,218 736,218 736,168 ; 635,120 712,120 712,162 ; 672,86 678,86 ; 672,114 678,114 ; 672,126 678,126 ; 672,154 678,154 ; 679,30.32 701,30.32 ; 679,69.69 701,69.69 ; 679,170.32 701,170.32 ; 679,209.69 701,209.69 ; 735,41 745,31 ; 741,211 749,219 831,219 ; 756,164 764,172 ; 838,170 838,226 ; 909,172.01 909,225 ; 995.35,44.71 989.44,44.71 989.44,65.38 987,67.82 987,170.22 989.44,172.66 989.44,194.32 995.35,194.32 ; 1094.65,44.71 1100.56,44.71 1100.56,65.38 1103,67.82 1103,170.22 1100.56,172.66 1100.56,194.32 1094.65,194.32 ; 831,219 824,226 824,227 824,211.5 824,212 831,219
  text ".PCB_Rev" at 2376.24,14.52 h60
  text "TIDA-00165" at 2723.06,11.83 h60
  text ".Layer_Name" at 577,-858.49 h60
Top Paste:
  text ".Layer_Name" at 577,-858.49 h60
Bottom Paste:
  text ".Layer_Name" at 577,-858.49 h60
Top Solder:
  text ".Layer_Name" at 577,-858.49 h60
  text ".Layer_Name" at 577,-858.49 h60
Bottom Solder:
  text ".Layer_Name" at 577,-858.49 h60
Drill Guide:
  text ".Layer_Name" at 577,-858.49 h60
M1 Board Outline:
  the board outline again, w10
  text ".Layer_Name" at 590,-863 h60
M2 Board Dimensions:
  rectangle: 124.5,-410.5 499.5,-285.5
  rectangle: -0.5,-285.5 124.5,-160.5
  lines w7: -0.5,-285.5 999.5,-285.5 ; 124.5,-410.5 124.5,-160.5 ; 249.5,-410.5 249.5,-160.5 ; 499.5,-410.5 499.5,-160.5 ; 749.5,-410.5 749.5,-160.5 ; -0.5,-410.5 -0.5,-160.5 999.5,-160.5 999.5,-410.5 -0.5,-410.5
  lines w10: -0.5,-475.5 -0.5,-455.5 ; 59.5,-485.5 -0.5,-465.5 ; 59.5,-445.5 -0.5,-465.5 ; 223.58,-465.5 -0.5,-465.5 ; 775.42,-465.5 999.5,-465.5 ; 939.5,-485.5 999.5,-465.5 ; 939.5,-445.5 999.5,-465.5 ; 999.5,-475.5 999.5,-455.5
  text "1000 (mil)" at 233.58,-501.49 h60
M3 3D STEP Top:
  text ".Layer_Name" at 577,-858.49 h60
M4 3D STEP Bottom:
  text ".Layer_Name" at 577,-858.49 h60
M5 Assembly Top:
  circle w12: c122.04,51.23 r6
  circle w10: c2116.27,128.12 r5.43
  lines w10: -292,-930.17 6308,-930.17 ; -292,-726.83 6310,-726.83 ; -292,-523.5 -292,-1133.5 3713,-1133.5 6310,-1133.5 6310,-523.5 -291.5,-523.5 -291.5,-1133.5 1284,-1133.5 ; 2173,-1133.5 2173,-523.5 ; 3440,-726.83 3440,-523.5 ; 4280,-726.83 4280,-523.5 ; 4902,-1140 4902,-937.17
  text "COMPONENTS MARKED 'DNP' SHOULD NOT BE POPULATED." at 1153.5,-318.5 h60
  text "ASSEMBLY VARIANT:" at 1153,-434 h60
  text ".VariantName" at 2189,-434 h60
  text "PCB VIEWED FROM TOP SIDE" at -228.5,-655.67 h60
  text "BOARD #:" at 2248,-655.67 h60
  text ".PRJ_Number" at 2793.5,-655.67 h60
  text "SVN REV:" at 4476,-655.67 h60
  text ".VersionControl_RevNumber" at 4982,-655.67 h60
  text "REV:" at 3562,-667 h60
  text ".PCB_Rev" at 3898,-667 h60
  text "IGNORE ->" at -228.5,-858.49 h60
  text "PLOT NAME =" at -228.5,-1064.34 h60
  text ".plot_File_Name" at 577,-1064.34 h60
  text "GENERATED    :" at 2250,-1064.34 h60
  text ".Print_Date" at 3119.5,-1064.34 h60
  text ".Print_Time" at 3848.5,-1064.34 h60
  text "TEXAS INSTRUMENTS" at 5113,-1064.34 h60
M6 Assembly Bottom:
  lines w10: -292.5,-727.33 6309.5,-727.33 ; -290.5,-930.67 6309.5,-930.67 ; 1115.5,-1140.5 1115.5,-937.67 ; 1737.5,-727.33 1737.5,-524 ; 2577.5,-727.33 2577.5,-524 ; 3844.5,-1134 3844.5,-524 ; 4733.5,-1134 6309,-1134 6309,-524 -292.5,-524 -292.5,-1134 2304.5,-1134 6309.5,-1134 6309.5,-524
  text "1" at 1108.83,189.12 h30
  text "COMPONENTS MARKED 'DNP' SHOULD NOT BE POPULATED." at 6102,-318 h60
  text ".VariantName" at 5058,-434 h60
  text "ASSEMBLY VARIANT:" at 6097,-434 h60
  text ".PRJ_Number" at 3295,-654 h60
  text ".VersionControl_RevNumber" at 1035.5,-656.17 h60
  text "SVN REV:" at 1541.5,-656.17 h60
  text ".PCB_Rev" at 2088,-656.17 h60
  text "REV:" at 2379.5,-656.17 h60
  text "BOARD #:" at 3769.5,-656.17 h60
  text "PCB VIEWED FROM BOTTOM SIDE" at 6246,-656.17 h60
  text "IGNORE ->" at 2547.85,-858.49 h60
  text "TEXAS INSTRUMENTS" at 904.5,-1064.84 h60
  text ".Print_Time" at 2169,-1064.84 h60
  text ".Print_Date" at 2898,-1064.84 h60
  text "GENERATED    :" at 3767.5,-1064.84 h60
  text ".plot_File_Name" at 5440.5,-1064.84 h60
  text "PLOT NAME =" at 6246,-1064.84 h60
M9 Title Sheet:
  drawing of 57 lines, arcs and shapes, not listed
  text "1" at 739.84,8036.5 h70
  text "2" at 3235.5,8036.5 h70
  text "3" at 5724.84,8036.5 h70
  text "4" at 8231.51,8036.5 h70
  text "5" at 10730.5,8036.5 h70
  text "6" at 13235.5,8036.5 h70
  text "A" at -416.5,6893.5 h70
  text "A" at 14383.5,6893.5 h70
  text "B" at -416.5,4513.5 h70
  text "B" at 14383.5,4513.5 h70
  text "C" at -416.5,2138.5 h70
  text "C" at 14383.5,2138.5 h70
  text "PROJECT TITLE:" at 11343.5,277.5 h45
  text ".PRJ_Title" at 11469,146 h100
  text "DESIGNED FOR:" at 11343.5,-23.5 h45
  text ".PRJ_Customer" at 11393.5,-163.5 h70
  text "D" at -416.5,-231.5 h70
  text "D" at 14383.5,-231.5 h70
  text "FILE NAME:" at 11343.5,-323.5 h45
  text ".PCB_File_Name_No_Path" at 11393.5,-443.5 h70
  text "Texas Instruments (TI) and/or its licensors do not warrant the accuracy or completeness of this specification" at 6374,-605.34 h45
  text "ENGINEER:" at 11343.5,-613.5 h45
  text "LAYOUT BY:" at 12848.5,-613.5 h45
  text "or any information contained therein. TI and/or its licensors do not warrant that this design will meet" at 6329.01,-718 h45
  text ".PRJ_Engineer" at 11393.5,-768.49 h70
  text "the specifications, will be suitable for your application or fit for any particular purpose, or will operate in" at 6329.01,-830.67 h45
  text "ALTIUM DESIGNER VERSION:" at 12848.5,-923.5 h45
  text "an implementation. TI and/or its licensors do not warrant that the design is production worthy. You should" at 6329.01,-943.33 h45
  text "completely validate and test your design implementation to confirm the system functionality for your application." at 6374,-1056 h45
  text ".print_Scale" at 11393.5,-1056.83 h70
  text ".Application_BuildNumber" at 12899,-1056.83 h70
  text "1" at 739.84,-1263.5 h70
  text "2" at 3235.5,-1263.5 h70
  text "3" at 5724.84,-1263.5 h70
  text "4" at 8231.51,-1263.5 h70
  text "5" at 10730.5,-1263.5 h70
  text "6" at 13235.5,-1263.5 h70
M10 Fab Notes:
  drawing of 220 lines, arcs and shapes, not listed
  text "DESIGN INFORMATION" at 12381.02,6810 h60
  text "(REFER ALSO ARRAY/PANEL PROFILING INFORMATION)" at 12019.46,6648.29 h60
  text "BOARD SIZE" at 11333.46,6644 h60
  text "X" at 12301.46,6516.18 h60
  text "2800MIL" at 12532.78,6516.18 h60
  text "235.83MIL" at 11754.22,6513.57 h60
  text "Number of Layers :" at 11736.46,6319 h60
  text "4" at 12831.27,6309 h60
  text "MIN. TRACK WIDTH:" at 11736.46,6180 h60
  text "6" at 12832.7,6180 h60
  text "MIL" at 12987.46,6180 h60
  text "MIN. CLEARANCE:" at 11736.46,6048 h60
  text "MIL" at 12987.46,6048 h60
  text "4.95" at 12744,6046 h60
  text "MIN. VIA PAD SIZE:" at 11736.46,5916 h60
  text "18" at 12802.71,5916 h60
  text "MIL" at 12987.46,5916 h60
  text "EXTERNAL" at 13236,5777 h60
  text "0.111mm (4.39MIL)" at 12431.46,5774.29 h60
  text "MINIMUM ANNULAR RING" at 11407.23,5770 h60
  text "PER" at 11607.23,5652 h60
  text "IPC-D-275 CLASS 2 LEVEL C" at 11827.23,5652 h60
  text "MIL, HOLES" at 13315.46,5539.71 h60
  text "+/-" at 12923,5539 h60
  text "+/-" at 13777,5539 h60
  text "REGISTRATION TOLERANCES:" at 11407.23,5534 h60
  text "METAL" at 12607,5534 h60
  text "5" at 13183.2,5534 h60
  text "3" at 14016.2,5534 h60
  text "MIL" at 14132.46,5534 h60
  text "MATERIAL:" at 11332.46,5324.54 h60
  text "FR-4 High Tg" at 12318.9,5184.21 h60
  text "FR-408" at 11753.46,5175.64 h60
  text "OTHER" at 13241.46,5175.64 h60
  text "X" at 11600,5175 h60
  text "63 MIL (1.6mm) +/-10%" at 12073.56,5012.92 h60
  text "THICKNESS:" at 11407.23,5008.64 h60
  text "X" at 11945.4,5008.64 h60
  text "OTHER" at 13358.46,5008.64 h60
  text "TOLERANCE:" at 11407.23,4850.64 h60
  text "X" at 12246.53,4850.64 h60
  text "ANSI IPC-6012 TYPE 3 CLASS 2" at 12433.48,4850.64 h60
  text "OTHER +/-" at 12433.46,4694.64 h60
  text "BOW & TWIST:" at 11407.23,4537.64 h60
  text "X" at 12246.53,4537.64 h60
  text "ANSI IPC-6012 TYPE 3 CLASS 2" at 12433.48,4537.64 h60
  text "OTHER +/-" at 12433.46,4379.13 h60
  text "COPPER THICKNESS (FINISHED):" at 11332.46,4243.64 h60
  text "1.4MIL (1oz)" at 12212.46,4090.92 h60
  text "2MIL (1.4oz)" at 12979.46,4090.92 h60
  text "2.8MIL (2oz)" at 13706.46,4090.92 h60
  text "OUTER:" at 11689.46,4086.64 h60
  text "X" at 12084,4086 h60
  text "1.4MIL (1oz)" at 12212.46,3933.92 h60
  text "2.8MIL (2oz)" at 12979.46,3933.92 h60
  text "N/A" at 13706,3934.29 h60
  text "INNER SIGNAL:" at 11400.38,3929.64 h60
  text "X" at 12085.42,3929.64 h60
  text "DRILLING:" at 11332.46,3790.64 h60
  text "REFERENCE:" at 11407.23,3673.64 h60
  text "X" at 12055.46,3673.64 h60
  text "AS SHOWN" at 12242.46,3673.64 h60
  text "X" at 12956.46,3673.64 h60
  text "NC_DRILL FILES" at 13093.46,3673.64 h60
  text "PTH MIN COPPER THICKNESS:" at 11407.23,3515.64 h60
  text "X" at 12757.46,3515.64 h60
  text "1MIL" at 12894.46,3515.64 h60
  text "OTHER" at 13391.46,3515.64 h60
  text "BOARD FINISH:" at 11332.46,3356.64 h60
  text "SILKSCREEN:" at 11487.68,3238.64 h60
  text "X" at 12436.46,3238.64 h60
  text "TOP" at 12562.46,3238.64 h60
  text "X" at 12946.46,3238.64 h60
  text "BOTTOM" at 13073.46,3238.64 h60
  text "SILKSCREEN COLOR:" at 11487.68,3071.64 h60
  text "X" at 12435.42,3071.64 h60
  text "WHITE" at 12562.46,3071.64 h60
  text "OTHER" at 13073.46,3071.64 h60
  text "SOLDER RESIST COLOR:" at 11487.68,2901.64 h60
  text "X" at 12055.42,2742.44 h60
  text "GREEN" at 12182.46,2742.44 h60
  text "BLUE" at 12773.46,2742.44 h60
  text "OTHER" at 13311.46,2742.44 h60
  text "IMMERSION GOLD (ENIG)" at 12393.46,2553.92 h60
  text "ENEPIG" at 13731,2550.64 h60
  text "SURFACE FINISH:" at 11332.46,2549.64 h60
  text "X" at 12206.51,2549.64 h60
  text "IMM. TIN/SILVER OR EQUIV" at 11662,2392.64 h60
  text "OTHER" at 13093.46,2392.64 h60
  text "ARRAY/PANEL:" at 11332.46,2213.64 h60
  text "CUT AND TRIM PER MECH LAYER 1" at 12393.46,2209.35 h60
  text "N.C. ROUTE" at 12393.46,2057.64 h60
  text "X" at 13072.46,2057.64 h60
  text "V. SCORE" at 13259.46,2057.64 h60
  text "CERTIFICATION:" at 11332.46,1920.64 h60
  text "MATERIALS AND WORKMANSHIP FOR ALL PCBS" at 12057.46,1920.64 h60
  text "TO MEET OR EXCEED THE REQUIREMENTS OF:" at 12057.46,1822.64 h60
  text "X" at 11683.96,1686.13 h60
  text "ANSI IPC-A-600F CLASS ->" at 11822.96,1686.13 h60
  text "X" at 13462.02,1686.13 h60
  text "2" at 13580.96,1686.14 h60
  text "1" at 13265.96,1684.64 h60
  text "3" at 13934.96,1684.64 h60
  text "X" at 11686.02,1526.64 h60
  text "UL 94V-0" at 11822.96,1526.64 h60
  text "X" at 12498.02,1526.64 h60
  text "RoHS" at 12634.96,1526.64 h60
  text "OTHER" at 13279.36,1526.64 h60
  text "PER ORDER" at 13676.42,1526.64 h60
  text "ADDITIONAL REQUIREMENTS:" at 11332.46,1385.64 h60
  text "VIA TENTING:" at 12807,1290 h60
  text "X" at 13595.29,1290.11 h60
  text "YES" at 13378.67,1280.92 h60
  text "NO" at 13773.47,1280.69 h60
  text "MICROSECTION:" at 11407.23,1270.64 h60
  text "YES" at 12312.96,1270.64 h60
  text "REQUIRED" at 13174.46,1114.49 h60
  text "BARE BOARD ELEC. TEST:" at 11407.23,1111.64 h60
  text "NONE" at 12712.96,1111.64 h60
  text "X" at 13047.46,1111.64 h60
  text "PER ORDER" at 13766.46,1111.64 h60
  text "MANUFACTURER'S UL:" at 11407.23,954.64 h60
  text "RAIL" at 12572.96,950.35 h60
  text "METAL" at 13064.77,950.35 h60
  text "X" at 13440,950 h60
  text "SILK" at 13576.46,950.35 h60
M11 Gerber Information:
  lines w10: -292,-930.17 6308,-930.17 ; -292,-726.83 6310,-726.83 ; -292,-523.5 -292,-1133.5 3713,-1133.5 6310,-1133.5 6310,-523.5 -291.5,-523.5 -291.5,-1133.5 1284,-1133.5 ; 2173,-1133.5 2173,-523.5 ; 3440,-726.83 3440,-523.5 ; 4280,-726.83 4280,-523.5 ; 4902,-1140 4902,-937.17
  text "ALL ARTWORK VIEWED FROM TOP SIDE" at -228.5,-655.67 h60
  text "BOARD #:" at 2248,-655.67 h60
  text ".PRJ_Number" at 2793.5,-655.67 h60
  text "SVN REV:" at 4476,-655.67 h60
  text ".VersionControl_RevNumber" at 4982,-655.67 h60
  text "REV:" at 3562,-667 h60
  text ".PCB_Rev" at 3898,-667 h60
  text "LAYER NAME =" at -228.5,-858.49 h60
  text "PLOT NAME =" at -228.5,-1064.34 h60
  text ".plot_File_Name" at 577,-1064.34 h60
  text "GENERATED    :" at 2250,-1064.34 h60
  text ".Print_Date" at 3119.5,-1064.34 h60
  text ".Print_Time" at 3848.5,-1064.34 h60
  text "TEXAS INSTRUMENTS" at 5113,-1064.34 h60
M12 Stackup:
  lines w6: 11334.76,7641.3 14213.58,7641.3 ; 11334.76,7745.7 14213.58,7745.7 ; 11274.76,6973.68 ccw(c11308.76,6973.68) 11308.76,6939.68 14239.58,6939.68 ccw(c14239.58,6973.68) 14273.58,6973.68 14273.58,7837.17 ccw(c14239.58,7837.17) 14239.58,7871.17 11308.76,7871.17 ccw(c11308.76,7837.17) 11274.76,7837.17 11274.76,6973.68
  text "Layer Stack Up Detail for: TIDA-00165.PcbDoc" at 11334.76,7773.04 h48
  text "Layer" at 11334.76,7706.7 h24
  text "Gerber" at 12340.18,7706.7 h24
  text "Copper" at 13013.31,7706.7 h24
  text "Dielectric" at 13725.62,7706.7 h24
  text "Name" at 11334.76,7658.7 h24
  text "Document" at 12340.18,7658.7 h24
  text "Thickness" at 13013.31,7658.7 h24
  text "Material" at 13725.62,7658.7 h24
  text "Top Solder Mask" at 11334.76,7589.79 h34
  text "(.GTS)" at 12340.18,7589.79 h34
  text "Solder Resist" at 13725.62,7589.79 h34
  text "Top Layer" at 11334.76,7492.76 h34
  text "(.GTL)" at 12340.18,7492.76 h34
  text "1.4mil" at 13013.31,7492.76 h34
  text "FR-4" at 13725.62,7444.24 h34
  text "GND" at 11334.76,7395.73 h34
  text "(.G1)" at 12340.18,7395.73 h34
  text "1.4mil" at 13013.31,7395.73 h34
  text "FR-4" at 13725.62,7347.21 h34
  text "VCC" at 11334.76,7298.7 h34
  text "(.G2)" at 12340.18,7298.7 h34
  text "1.4mil" at 13013.31,7298.7 h34
  text "FR-4" at 13725.62,7250.18 h34
  text "Bottom Layer" at 11334.76,7201.67 h34
  text "(.GBL)" at 12340.18,7201.67 h34
  text "1.4mil" at 13013.31,7201.67 h34
  text "Bottom Solder Mask" at 11334.76,7104.64 h34
  text "(.GBS)" at 12340.18,7104.64 h34
  text "Solder Resist" at 13725.62,7104.64 h34
M13 Component Bodies Top:
  text ".Layer_Name" at 577,-858.49 h60
M14 Component Bodies Bottom:
  text ".Layer_Name" at 577,-858.49 h60
M15 Courtyards Top:
  text ".Layer_Name" at 577,-858.49 h60
M16 Courtyards Bottom:
  text ".Layer_Name" at 577,-858.49 h60
Drill Drawing:
  text ".LEgend" at 4058.72,540.11 h60
  text "DRILL TOLERANCE" at 4067.72,416.52 h60
  text "FOR NPTH +/- 2MIL" at 4068.14,307.09 h60
  text "EXCEPT 8MIL DRILL +/- 3MIL" at 4073.26,191.42 h60
  text "FOR 8 MIL DRILL +0/-8 MIL" at 4072.68,81.01 h60
  text ".Layer_Name" at 577,-858.49 h60

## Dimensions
0,0 to 0,235.83 on M2 Board Dimensions
0,235.83 to 2800,236 on M2 Board Dimensions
